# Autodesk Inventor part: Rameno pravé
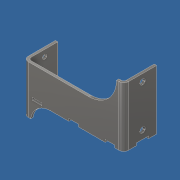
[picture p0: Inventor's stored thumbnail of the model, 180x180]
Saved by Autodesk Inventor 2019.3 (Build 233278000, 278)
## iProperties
Created: 2019-02
Part Number: Rameno pravé
Material: Nerezová ocel, austenitická
Document SubType Name: Plech
Designer: B-hon
Density: 8 g/cm^3
Sheet Metal Rule: Výchozí_mm
Appearance: Pololeštěná
Author: B-hon
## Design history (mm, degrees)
node "Plocha3"
  sketch "Náčrt4"
    geometry: L1 (0, 0)-(125, 0); L2 (125, 0)-(125, 95); L3 (125, 95)-(0, 95); L4 (0, 95)-(0, 0)
    constraints: 8 end point, 2 parallel, 1 horizontal, 1 perpendicular
    dimensions: "d21" = 125 distance of L3.end L2.end; "d22" = 95 distance of L2.end L1.end
node "Obruba2"
node "Obruba3"
sketch "Náčrt7"
  geometry: L1 (-8.449, 60)-(-3.667, 60); L2 (-3.667, 60)-(-3.667, 60); L3 (-3.667, 60)-(116, 60); L4 (116, 60)-(116, 100.088); L5 (116, 100.088)-(-8.681, 99.353); L6 (-8.681, 99.353)-(-8.449, 60); L7 (6, 95)-(6, 0) reference; L8 (119, 0)-(119, 95) reference; L9 (119, 0)-(6, 0) reference; 1 further point
  constraints: 12 end point, 4 perpendicular, 1 horizontal
  dimensions: "d45" = 3 distance between parallel lines of L8 L4; "d46" = 60 distance between parallel lines of L9 L3; "d47" = 60 distance between parallel lines of L9 L1
extrude "Vysunutí1" cut sketch "Náčrt7" distance "d48" = 100; taper "d49" = 0 deg
fillet "Zaoblení2" dims "d51" = 35
sketch "Náčrt8"
  geometry: L1 (9, 21)-(200.584, 21); L2 (200.584, 21)-(200.584, -6.662); L3 (200.584, -6.662)-(9, -6.662); L4 (9, -6.662)-(9, 21); L5 (81, 60)-(6, 60) reference; L6 (6, 60)-(6, 0) reference; 1 further point
  constraints: 8 end point, 2 parallel, 1 horizontal, 1 perpendicular
  dimensions: "d52" = 39 distance between parallel lines of L5 L1; "d53" = 3 distance between parallel lines of L6 L4
extrude "Vysunutí2" cut sketch "Náčrt8" distance "d54" = 100; taper "d55" = 0 deg
fillet "Zaoblení3" dims "d56" = 25
sketch "Náčrt9"
  geometry: L1 (0, 0)-(0, 60) reference; L2 (34, 0)-(0, 0) reference; 4 further points
  constraints: 1 horizontal alignment
  dimensions: "d57" = 6 distance from line of L1 point (6, 7); "d58" = 21 distance of point (27, 7) point (6, 7); "d59" = 7 distance from line of L2 point (6, 7); "d60" = 45 vertical distance of point (27, 7) point (16.5, 52); "d61" = 10.5 horizontal distance of point (27, 7) point (16.5, 52) (= 0.5 x d58)
hole "Díra1" sketch "Náčrt9" at (16.5, 52), (27, 7), (6, 7) diameter "d62" = 5.5; stored, may be unused: countersink angle "d66" = 90 deg, drill point angle "d68" = 118 deg; dims "d63" = 12, "d64" = 4, "d65" = 2, "d67" = 3 (= Tloušťka)
sketch "Náčrt10"
  geometry: L1 (0, 0)-(35, 0) reference; C1 r 2.75 at (28, -88) reference; C2 r 2.75 at (7, -88) reference; C3 r 2.75 at (17.5, -43) reference; 3 further points
  constraints: 2 vertical alignment
  dimensions: "d69" = 9 distance from line of point (17.5, -9) L1; "d70" = 52 distance of point (17.5, -61) point (17.5, -9)
hole "Díra2" sketch "Náčrt10" at (17.5, -61), (17.5, -9) diameter "d71" = 6.6; stored, may be unused: countersink angle "d75" = 90 deg, drill point angle "d77" = 118 deg; dims "d72" = 12, "d73" = 4, "d74" = 2, "d76" = 3 (= Tloušťka)
sketch "Náčrt15"
  geometry: L1 (-119, 21)-(-33.678, 21) reference; L2 (-114, 24)-(-102, 24); L3 (-102, 24)-(-102, 21); L4 (-102, 21)-(-114, 21); L5 (-114, 21)-(-114, 24); L6 (-119, 95)-(-119, 21) reference; 1 further point
  constraints: 8 end point, 2 parallel, 1 horizontal, 1 perpendicular, 1 point on line
  dimensions: "d104" = 12 distance of L3.end L4.end; "d105" = 3 distance of L2.end L3.end; "d106" = 5 distance between parallel lines of L6 L5
extrude "Vysunutí7" cut sketch "Náčrt15" distance "d107" = 300; taper "d108" = 0 deg
pattern_linear "Obdélníkové pole3" dims "d111" = 45.5
sketch "Náčrt16"
  geometry: L1 (10, -71)-(25, -71); L2 (25, -71)-(25, -74); L3 (25, -74)-(10, -74); L4 (10, -74)-(10, -71); L5 (0, -74)-(35, -74) reference; L6 (-6, -74)-(-6, 0) reference; 1 further point
  constraints: 8 end point, 2 parallel, 1 horizontal, 1 perpendicular
  dimensions: "d112" = 0 distance between parallel lines of L5 L3; "d113" = 3 distance of L1.end L2.end; "d114" = 15 distance of L2.end L3.end; "d115" = 16 distance between parallel lines of L6 L4
extrude "Vysunutí8" cut sketch "Náčrt16" distance "d116" = 300; taper "d117" = 0 deg
node "Těleso3"
feature "Deska4" dims "d23" = 3 (= Tloušťka)
sketch "Náčrt5"
  geometry: L1 through (47.5, 0) direction (-1, 0); L2 through (0, -20) direction (0, -1); L3 (0, -40)-(95, -40); L4 (95, -40)-(95, 0)
  constraints: 6 end point, 1 horizontal, 1 perpendicular, 1 vertical
feature "Deska5" dims "d23" = 3 (= Tloušťka), "d24" = 3 (= ŠířkaVýštipu), "d25" = 1.5 (= HloubkaVýštipu), "d26" = 6 (= MinimálníZbytek), "d27" = 3 (= PřechodovýPoloměr), "d28" = 40, "d29" = 90 deg, "d30" = 3 (= PoloměrOhybu), "d31" = 12 (= VelikostRohovéhoVýštipu), "d32" = 3 (= VelikostMezery), "d33" = 3 (= VelikostJacobihoPoloměru), "MezeraVystřižení" = 0.01
feature "Ohyb2" dims "d23" = 3 (= Tloušťka), "d24" = 3 (= ŠířkaVýštipu), "d25" = 1.5 (= HloubkaVýštipu), "d26" = 6 (= MinimálníZbytek), "d27" = 3 (= PřechodovýPoloměr), "d28" = 40, "d29" = 90 deg, "d30" = 3 (= PoloměrOhybu), "MezeraVystřižení" = 0.01
feature "Roh2" dims "d28" = 40, "d29" = 90 deg, "d31" = 12 (= VelikostRohovéhoVýštipu), "d32" = 3 (= VelikostMezery), "d33" = 3 (= VelikostJacobihoPoloměru)
sketch "Náčrt6"
  geometry: L1 through (47.5, 0) direction (-1, 0); L2 through (0, -20.5) direction (0, -1); L3 (0, -41)-(95, -41); L4 (95, -41)-(95, 0)
  constraints: 6 end point, 1 horizontal, 1 perpendicular, 1 vertical
feature "Deska6" dims "d23" = 3 (= Tloušťka), "d34" = 3 (= ŠířkaVýštipu), "d35" = 1.5 (= HloubkaVýštipu), "d36" = 6 (= MinimálníZbytek), "d37" = 3 (= PřechodovýPoloměr), "d38" = 41, "d39" = 90 deg, "d40" = 3 (= PoloměrOhybu), "d41" = 12 (= VelikostRohovéhoVýštipu), "d42" = 3 (= VelikostMezery), "d43" = 3 (= VelikostJacobihoPoloměru), "MezeraVystřižení" = 0.01
feature "Ohyb3" dims "d23" = 3 (= Tloušťka), "d34" = 3 (= ŠířkaVýštipu), "d35" = 1.5 (= HloubkaVýštipu), "d36" = 6 (= MinimálníZbytek), "d37" = 3 (= PřechodovýPoloměr), "d38" = 41, "d39" = 90 deg, "d40" = 3 (= PoloměrOhybu), "MezeraVystřižení" = 0.01
feature "Roh3" dims "d38" = 41, "d39" = 90 deg, "d41" = 12 (= VelikostRohovéhoVýštipu), "d42" = 3 (= VelikostMezery), "d43" = 3 (= VelikostJacobihoPoloměru)
other parameters: "Tloušťka" = 3 (derived), "KSoučinitel" = 4.4, "PoloměrOhybu" = 3 (= Tloušťka), "ŠířkaVýštipu" = 3 (= Tloušťka), "HloubkaVýštipu" = 1.5 (= 0.5 x Tloušťka), "VelikostRohovéhoVýštipu" = 12 (= 4 x Tloušťka), "MinimálníZbytek" = 6 (= 2 x Tloušťka), "PřechodovýPoloměr" = 3 (= PoloměrOhybu), "VelikostJacobihoPoloměru" = 3 (= PoloměrOhybu), "VelikostMezery" = 3 (= Tloušťka)
